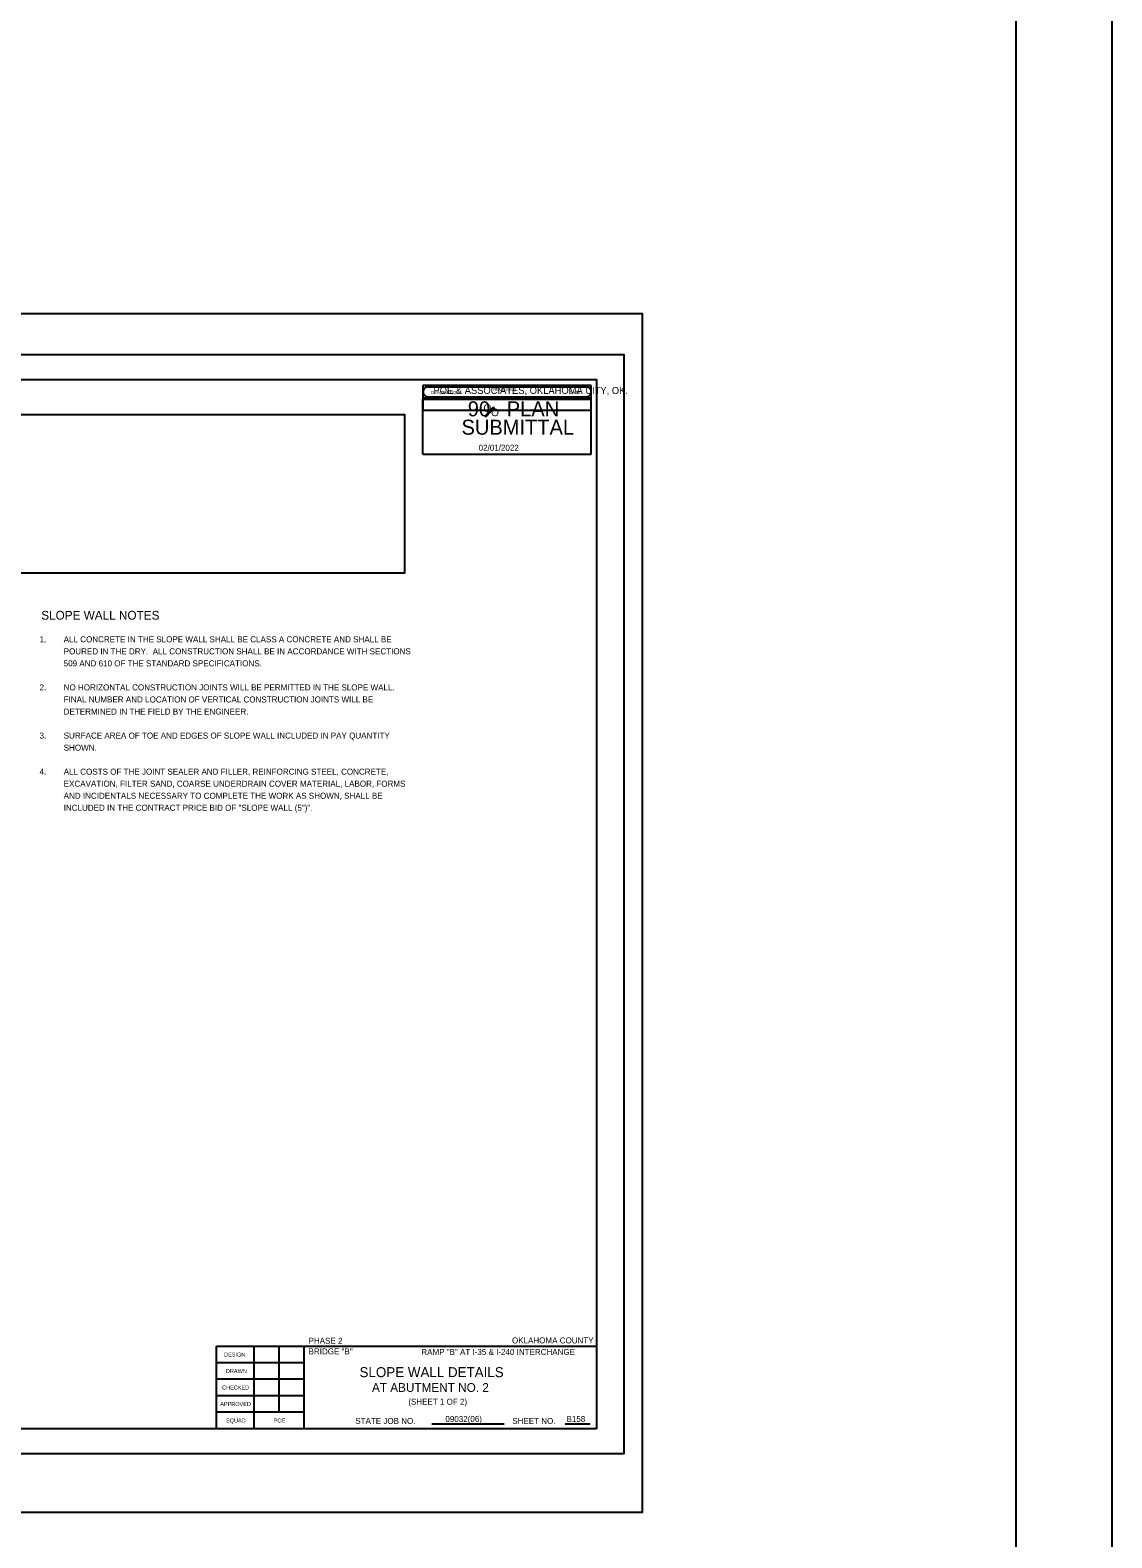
# Model space of a CAD drawing. Extents: x 570 to 2152770, y 726 to 139926.
# Drawn here: x 2152545.4 to 2152718.5, y 139443.6 to 139685 of the extents above; entities that cross this region are included whole.
import ezdxf

# ---------------------------------------------------------------- set-up
doc = ezdxf.new("R2010")
doc.units = 0
for name, color, linetype in [('S', 7, 'Continuous'), ('SHT_Plot_Shape_Full', 7, 'Continuous'), ('SHT_Plot_Shape_Half', 7, 'Continuous'), ('SHT_Sheet_Border', 7, 'Continuous'), ('SHT_Stamp_90_Submit', 7, 'Continuous'), ('SHT_Stamp_Rev_Block', 7, 'Continuous'), ('SHT_Standard_Sheet_Lines', 7, 'Continuous'), ('SHT_Standard_Sheet_Txt', 7, 'Continuous'), ('T', 7, 'Continuous'), ('T-Subtitle', 7, 'Continuous'), ('T-Title', 7, 'Continuous')]:
    doc.layers.add(name, color=color, linetype=linetype)

msp = doc.modelspace()

# ---------------------------------------------------------------- linework, layer by layer
at = {"layer": 'S'}
for points in [[(2151790.38, 139812.49), (2152718.5, 139812.49), (2152718.5, 139247.24), (2151790.38, 139247.24)], [(2152319.83, 139266.32), (2152703.21, 139266.32), (2152703.21, 139793.9), (2152319.83, 139793.9)]]:
    msp.add_lwpolyline(points, close=True, dxfattribs=at)
at = {"layer": 'SHT_Plot_Shape_Full'}
msp.add_lwpolyline([(2152355.32, 139639.66), (2152643.32, 139639.66), (2152643.32, 139447.66), (2152355.32, 139447.66)], close=True, dxfattribs=at)
at = {"layer": 'SHT_Plot_Shape_Half'}
msp.add_lwpolyline([(2152368.42, 139633.06), (2152640.42, 139633.06), (2152640.42, 139457.06), (2152368.42, 139457.06)], close=True, dxfattribs=at)
at = {"layer": 'SHT_Sheet_Border'}
for p, q in [((2152575.22, 139461.06), (2152575.22, 139474.26)), ((2152575.22, 139474.26), (2152636.02, 139474.26)), ((2152589.22, 139461.06), (2152589.22, 139474.27)), ((2152589.22, 139461.06), (2152589.22, 139474.27))]:
    msp.add_line(p, q, dxfattribs=at)
msp.add_lwpolyline([(2152636.02, 139461.06), (2152384.02, 139461.06), (2152384.02, 139629.06), (2152636.02, 139629.06)], close=True, dxfattribs=at)
at = {"layer": 'SHT_Stamp_90_Submit'}
for p, q in [((2152609.06, 139627.9), (2152634.39, 139627.9)), ((2152608.26, 139625.9), (2152635.19, 139625.9)), ((2152608.26, 139617.11), (2152608.26, 139625.9)), ((2152609.06, 139626.3), (2152634.39, 139626.3)), ((2152635.19, 139617.11), (2152635.19, 139625.9)), ((2152618.21, 139623.2), (2152619.45, 139624.58)), ((2152618.21, 139623.2), (2152618.45, 139623.2)), ((2152618.35, 139623.2), (2152619.6, 139624.58)), ((2152618.39, 139623.2), (2152619.64, 139624.58)), ((2152618.45, 139623.2), (2152619.7, 139624.58)), ((2152619.45, 139624.58), (2152619.7, 139624.58)), ((2152608.26, 139617.11), (2152635.19, 139617.11))]:
    msp.add_line(p, q, dxfattribs=at)
for centre, start, end in [((2152609.07, 139627.11), 89.9952, 270), ((2152634.39, 139627.11), 270, 90.0048)]:
    msp.add_arc(centre, 0.8, start, end, dxfattribs=at)
at = {"layer": 'SHT_Stamp_Rev_Block'}
for p, q in [((2152608.26, 139628.1), (2152608.26, 139624.1)), ((2152635.19, 139628.1), (2152608.26, 139628.1)), ((2152635.19, 139624.1), (2152635.19, 139628.1)), ((2152635.19, 139626.1), (2152608.26, 139626.1)), ((2152635.19, 139624.1), (2152608.26, 139624.1))]:
    msp.add_line(p, q, dxfattribs=at)
at = {"layer": 'SHT_Standard_Sheet_Lines'}
for p, q in [((2152581.22, 139461.06), (2152581.22, 139474.27)), ((2152585.22, 139463.71), (2152585.22, 139474.27)), ((2152609.7, 139461.83), (2152621.23, 139461.83)), ((2152609.7, 139461.83), (2152621.23, 139461.83)), ((2152631.02, 139461.83), (2152635.04, 139461.83)), ((2152631.02, 139461.83), (2152635.04, 139461.83))]:
    msp.add_line(p, q, dxfattribs=at)
for points in [[(2152589.22, 139471.62), (2152575.22, 139471.62)], [(2152589.22, 139468.98), (2152575.22, 139468.98)], [(2152589.22, 139466.34), (2152575.22, 139466.34)], [(2152589.22, 139463.7), (2152575.22, 139463.7)]]:
    msp.add_lwpolyline(points, dxfattribs=at)
at = {"layer": 'T'}
msp.add_lwpolyline([(2152542.67, 139598.1), (2152605.38, 139598.1), (2152605.38, 139623.41), (2152542.67, 139623.41)], close=True, dxfattribs=at)

# ---------------------------------------------------------------- texts
at = {"layer": 'SHT_Stamp_90_Submit'}
for s, height, p in [('POE & ASSOCIATES, OKLAHOMA CITY, OK.', 1.12, (2152609.94, 139626.76)), ('90   PLAN', 2.4, (2152615.43, 139623.17)), ('O', 1.22, (2152617.93, 139623.88)), ('SUBMITTAL', 2.4, (2152614.43, 139620.23)), ('O', 1.22, (2152619.15, 139623.2)), ('02/01/2022', 0.96, (2152617.17, 139617.66))]:
    msp.add_text(s, height=height, dxfattribs=at).set_placement(p)
at = {"layer": 'SHT_Stamp_Rev_Block'}
for s, p in [('REVISIONS', (2152619.53, 139627.2)), ('DESCRIPTION', (2152609.54, 139626.72)), ('DATE', (2152631.7, 139626.76))]:
    msp.add_text(s, height=0.48, dxfattribs=at).set_placement(p)
at = {"layer": 'SHT_Standard_Sheet_Txt'}
for s, height, p in [('DESIGN', 0.64, (2152576.43, 139472.62)), ('DRAWN', 0.64, (2152576.72, 139469.98)), ('CHECKED', 0.64, (2152576.12, 139467.34)), ('APPROVED', 0.64, (2152575.81, 139464.7)), ('SQUAD', 0.64, (2152576.75, 139462.06)), ('POE', 0.64, (2152584.38, 139462.06)), ('STATE JOB NO.', 0.96, (2152597.43, 139461.83)), ('STATE JOB NO.', 0.96, (2152597.43, 139461.83)), ('SHEET NO. ', 0.96, (2152622.55, 139461.83)), ('SHEET NO. ', 0.96, (2152622.55, 139461.83))]:
    msp.add_text(s, height=height, dxfattribs=at).set_placement(p)
at = {"layer": 'T'}
for s, height, p in [('1.', 0.964, (2152546.9, 139586.99)), ('ALL CONCRETE IN THE SLOPE WALL SHALL BE CLASS A CONCRETE AND SHALL BE', 0.9635, (2152550.76, 139586.99)), ('509 AND 610 OF THE STANDARD SPECIFICATIONS.', 0.9635, (2152550.76, 139583.13)), ('POURED IN THE DRY.  ALL CONSTRUCTION SHALL BE IN ACCORDANCE WITH SECTIONS', 0.9635, (2152550.76, 139585.06)), ('2.', 0.964, (2152546.9, 139579.28)), ('NO HORIZONTAL CONSTRUCTION JOINTS WILL BE PERMITTED IN THE SLOPE WALL.', 0.9635, (2152550.76, 139579.28)), ('FINAL NUMBER AND LOCATION OF VERTICAL CONSTRUCTION JOINTS WILL BE ', 0.9635, (2152550.76, 139577.35)), ('DETERMINED IN THE FIELD BY THE ENGINEER.', 0.9635, (2152550.76, 139575.42)), ('3.', 0.964, (2152546.9, 139571.57)), ('SURFACE AREA OF TOE AND EDGES OF SLOPE WALL INCLUDED IN PAY QUANTITY', 0.9635, (2152550.76, 139571.57)), ('SHOWN.', 0.964, (2152550.76, 139569.64)), ('4. ', 0.964, (2152546.9, 139565.79)), ('ALL COSTS OF THE JOINT SEALER AND FILLER, REINFORCING STEEL, CONCRETE,', 0.9635, (2152550.76, 139565.79)), ('EXCAVATION, FILTER SAND, COARSE UNDERDRAIN COVER MATERIAL, LABOR, FORMS', 0.9635, (2152550.76, 139563.86)), ('AND INCIDENTALS NECESSARY TO COMPLETE THE WORK AS SHOWN, SHALL BE', 0.9635, (2152550.76, 139561.93)), ('INCLUDED IN THE CONTRACT PRICE BID OF "SLOPE WALL (5")".', 0.9635, (2152550.76, 139560.01)), ('PHASE 2', 0.96, (2152589.95, 139474.66)), ('OKLAHOMA COUNTY', 0.96, (2152622.51, 139474.72)), ('BRIDGE "B"', 0.96, (2152589.95, 139472.96)), ('RAMP "B" AT I-35 & I-240 INTERCHANGE', 0.96, (2152608, 139472.88)), ('(SHEET 1 OF 2)', 0.9583, (2152605.92, 139464.91)), ('09032(06)', 0.96, (2152611.85, 139462.14)), ('B158', 0.96, (2152631.23, 139462.14))]:
    msp.add_text(s, height=height, dxfattribs=at).set_placement(p)
at = {"layer": 'T-Subtitle'}
for s, p in [('SLOPE WALL NOTES', (2152547.17, 139590.61)), ('AT ABUTMENT NO. 2', (2152600.1, 139466.96))]:
    msp.add_text(s, height=1.4062, dxfattribs=at).set_placement(p)
at = {"layer": 'T-Title'}
msp.add_text('SLOPE WALL DETAILS', height=1.6, dxfattribs=at).set_placement((2152598.11, 139469.32))

doc.saveas('drawing.dxf')
